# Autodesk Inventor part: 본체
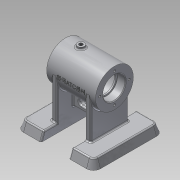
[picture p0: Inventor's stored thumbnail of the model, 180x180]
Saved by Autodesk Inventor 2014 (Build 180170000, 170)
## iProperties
Created: 2016-07
Part Number: 본체
Material: 알루미늄 6061
Document SubType Name: Modeling
Designer: net
Density: 2.71 g/cm^3
Appearance: 알루미늄 - 평지
Mass: 505.561 g
Surface Area: 530.336 cm^2
Volume: 186.554 cm^3
Author: net
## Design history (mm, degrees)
sketch "스케치1"
  geometry: C1 r 27 at (0, 0); 1 further point
  constraints: 1 centre point, 1 coincident
  dimensions: "d0" = 54 diameter of C1
extrude "돌출1" new body sketch "스케치1" stored distance "d1" = 70; taper "d2" = 0 deg
sketch "스케치2"
  geometry: C1 r 22 at (0, 0); 1 further point
  constraints: 1 centre point, 1 coincident
  dimensions: "d3" = 44 diameter of C1
extrude "돌출2" cut sketch "스케치2" stored distance "d4" = 42; taper "d5" = 0 deg
sketch "스케치3"
  geometry: C1 r 27 at (0, 0) reference; C2 r 14 at (0, 0)
  constraints: 1 centre point, 1 coincident
  dimensions: "d6" = 28 diameter of C2
extrude "돌출3" cut sketch "스케치3" stored distance "d7" = 42; taper "d8" = 0 deg
sketch "스케치4"
  geometry: C1 r 14 at (0, 0) reference; C2 r 27 at (0, 0) reference; C3 r 16 at (0, 0)
  constraints: 1 centre point, 1 coincident
  dimensions: "d9" = 32 diameter of C3
extrude "돌출4" cut sketch "스케치4" distance "d10" = 12; taper "d11" = 0 deg
sketch "스케치5"
  geometry: C1 r 14 at (0, 0) reference; C2 r 27 at (0, 0) reference; C3 r 16 at (0, 0)
  constraints: 1 centre point, 1 coincident
  dimensions: "d12" = 32 diameter of C3
extrude "돌출5" cut sketch "스케치5" distance "d13" = 12; taper "d14" = 0 deg
node "작업 평면1"
sketch "스케치6"
  geometry: L1 (-35, 27)-(-35, -27) reference; L2 (35, -27)-(35, 27) reference; L3 (-35, 0)-(35, 0); C1 r 5 at (-13, 0); 1 further point
  constraints: 2 end point, 2 midpoint, 1 centre point, 1 point on line
  dimensions: "d16" = 10 diameter of C1; "d17" = 22 distance of L3.start C1.centre
extrude "돌출6" join sketch "스케치6" stored distance "d18" = 12; taper "d19" = 0 deg
node "작업 평면3"
  node "작업 평면2"
sketch "스케치7"
  geometry: C1 r 6 at (0, 0); 1 further point
  constraints: 1 centre point, 1 coincident
  dimensions: "d22" = 12 diameter of C1
extrude "돌출7" join sketch "스케치7" stored distance "d23" = 10; taper "d24" = 0 deg
node "작업 평면4"
sketch "스케치9"
  geometry: L1 (-55, 50)-(-20, 50); L2 (-20, -50)-(-55, -50); L3 (-55, -50)-(-55, 50); L4 (0, 29.989)-(0, -29.989); L5 (55, 50)-(20, 50); L6 (55, -50)-(55, 50); L7 (20, -50)-(55, -50); L8 (-20, 50)-(20, 50); L9 (-20, -50)-(20, -50); C1 r 3 at (-42.5, 37.5); C2 r 3 at (-42.5, -37.5); C3 r 3 at (42.5, 37.5); C4 r 3 at (42.5, -37.5); 3 further points
  constraints: 18 end point, 6 symmetric about line, 4 centre point, 3 parallel, 2 midpoint, 1 coincident, 1 collinear, 1 horizontal, 1 horizontal alignment, 2 other
  dimensions: "d26" = 55 distance between parallel lines of L4 L3; "d27" = 100 distance of L2.end L1.start; "d28" = 35 distance of L1.start L1.end; "d29" = 6 diameter of C1; "d30" = 6 diameter of C2; "d31" = 12.5 distance from line of L2 C2.centre; "d32" = 12.5 distance from line of L3 C2.centre; "d33" = 12.5 distance from line of L1 C1.centre; "d34" = 12.5 distance from line of L3 C1.centre
extrude "돌출9" join sketch "스케치9" distance "d37" = 12; taper "d38" = -20 deg
sketch "스케치12"
  geometry: L1 (-23, 16)-(-35, 16) reference; L2 (-35, 16)-(-35, 27) reference; L3 (-35, 27)-(8, 27) reference; L4 (8, 27)-(8, 30) reference; L5 (8, 30)-(18, 30) reference; L6 (18, 30)-(18, 27) reference; L7 (18, 27)-(35, 27) reference; L8 (35, 27)-(35, 16) reference; L9 (35, 16)-(23, 16) reference; L10 (23, 16)-(23, 14) reference; L11 (23, 14)-(21, 14) reference; L12 (21, 14)-(21, 22) reference; L13 (21, 22)-(-21, 22) reference; L14 (-21, 22)-(-21, 14) reference; L15 (-21, 14)-(-23, 14) reference; L16 (-23, 14)-(-23, 16) reference; L17 (-35, -16)-(-23, -16) reference; L18 (-23, -16)-(-23, -14) reference; L19 (-23, -14)-(-21, -14) reference; L20 (-21, -14)-(-21, -22) reference; L21 (-21, -22)-(21, -22) reference; L22 (21, -22)-(21, -14) reference; L23 (21, -14)-(23, -14) reference; L24 (23, -14)-(23, -16) reference; L25 (23, -16)-(35, -16) reference; L26 (35, -16)-(35, -27) reference; L27 (35, -27)-(-35, -27) reference; L28 (-35, -27)-(-35, -16) reference; L29 (50.632, -58)-(55, -70) reference; L30 (55, -70)-(-55, -70) reference; L31 (-55, -70)-(-50.632, -58) reference; L32 (-50.632, -58)-(50.632, -58) reference; L33 (0, -70)-(0, 22); L34 (-20, -70)-(20, -70); L35 (20, -70)-(20, -58); L36 (20, -58)-(-20, -58); L37 (-20, -58)-(-20, -70); 1 further point
  constraints: 10 end point, 2 midpoint, 2 parallel, 2 point on line, 1 horizontal, 1 perpendicular
  dimensions: "d39" = 40 distance between parallel lines of L35 L37; "d40" = 20 distance between parallel lines of L33 L37
extrude "돌출10" cut sketch "스케치12" stored distance "d41" = 12; taper "d42" = 0 deg
sketch "스케치13"
  geometry: L1 (20, 50)-(20, -50) reference; L2 (-20, -50)-(-20, 50) reference; L3 (-20, 50)-(-55, 50) reference; L4 (-55, 50)-(-55, -50) reference; L5 (-55, -50)-(-20, -50) reference; L6 (-20, 50)-(20, 50); L7 (0, 50)-(0, -50); L8 (-20, 27)-(-28, 27); L9 (-28, 27)-(-28, -27); L10 (-28, -27)-(-20, -27); L11 (-20, -27)-(-20, 27); L12 (28, -27)-(20, -27); L13 (20, -27)-(20, 27); L14 (20, 27)-(28, 27); L15 (28, 27)-(28, -27); C1 r 3 at (-42.5, -37.5) reference; C2 r 3 at (-42.5, 37.5) reference; 1 further point
  constraints: 20 end point, 4 symmetric about line, 3 perpendicular, 2 parallel, 1 horizontal, 1 midpoint, 1 point on line
  dimensions: "d43" = 54 distance of L10.end L8.start; "d44" = 27 distance from line of point (0, 0) L8 (= 0.5 x d43); "d45" = 8 distance of L8.start L8.end
extrude "돌출11" join sketch "스케치13" stored distance "d46" = 12; taper "d47" = 0 deg
sketch "스케치14"
  geometry: L1 (23, -16)-(35, -16) reference; L2 (35, -16)-(35, -27) reference; L3 (35, -27)-(28, -27) reference; L4 (28, -27)-(28, -58) reference; L5 (28, -58)-(50.632, -58) reference; L6 (50.632, -58)-(55, -70) reference; L7 (55, -70)-(20, -70) reference; L8 (20, -70)-(20, -27) reference; L9 (20, -27)-(-20, -27) reference; L10 (-20, -27)-(-20, -70) reference; L11 (-20, -70)-(-55, -70) reference; L12 (-55, -70)-(-50.632, -58) reference; L13 (-50.632, -58)-(-28, -58) reference; L14 (-28, -58)-(-28, -27) reference; L15 (-28, -27)-(-35, -27) reference; L16 (-35, -27)-(-35, -16) reference; L17 (-35, -16)-(-23, -16) reference; L18 (-23, -16)-(-23, -14) reference; L19 (-23, -14)-(-21, -14) reference; L20 (-21, -14)-(-21, -22) reference; L21 (-21, -22)-(21, -22) reference; L22 (21, -22)-(21, -14) reference; L23 (21, -14)-(23, -14) reference; L24 (23, -14)-(23, -16) reference; L25 (35, 16)-(23, 16) reference; L26 (23, 16)-(23, 14) reference; L27 (23, 14)-(21, 14) reference; L28 (21, 14)-(21, 22) reference; L29 (21, 22)-(-21, 22) reference; L30 (-21, 22)-(-21, 14) reference; L31 (-21, 14)-(-23, 14) reference; L32 (-23, 14)-(-23, 16) reference; L33 (-23, 16)-(-35, 16) reference; L34 (-35, 16)-(-35, 27) reference; L35 (-35, 27)-(8, 27) reference; L36 (8, 27)-(8, 30) reference; L37 (8, 30)-(18, 30) reference; L38 (18, 30)-(18, 27) reference; L39 (18, 27)-(35, 27) reference; L40 (35, 27)-(35, 16) reference; L41 (-20, -48)-(20, -48); 1 further point
  constraints: 2 end point, 2 point on line, 1 perpendicular
  dimensions: "d48" = 21 distance between parallel lines of L15 L41
feature "리브1" sketch "스케치14" dims "d49" = 1, "d50" = 8, "d51" = 0, "d52" = 0, "d53" = 1, "d54" = 1
sketch "스케치15"
  geometry: L1 (10, 53.404)-(55, 53.404) reference; L2 (55, 53.404)-(55, 42.194) reference; L3 (55, 42.194)-(43, 42.194) reference; L4 (43, 42.194)-(43, 40.118) reference; L5 (43, 40.118)-(41, 40.118) reference; L6 (41, 40.118)-(41, 48.335) reference; L7 (41, 48.335)-(-1, 48.335) reference; L8 (-1, 48.335)-(-1, 40.118) reference; L9 (-1, 40.118)-(-3, 40.118) reference; L10 (-3, 40.118)-(-3, 42.194) reference; L11 (-3, 42.194)-(-15, 42.194) reference; L12 (-15, 42.194)-(-15, 53.404) reference; L13 (-15, 53.404)-(4, 53.404) reference; L14 (4, 53.404)-(4, 56.702) reference; L15 (4, 56.702)-(10, 56.702) reference; L16 (10, 56.702)-(10, 53.404) reference; L17 (0, -43.298)-(-35, -43.298) reference; L18 (-35, -43.298)-(-30.632, -31.298) reference; L19 (-30.632, -31.298)-(-8, -31.298) reference; L20 (-8, -31.298)-(-8, 0) reference; L21 (-8, 0)-(-15, 0) reference; L22 (-15, 0)-(-15, 11.21) reference; L23 (-15, 11.21)-(-3, 11.21) reference; L24 (-3, 11.21)-(-3, 13.286) reference; L25 (-3, 13.286)-(-1, 13.286) reference; L26 (-1, 13.286)-(-1, 5.069) reference; L27 (-1, 5.069)-(41, 5.069) reference; L28 (41, 5.069)-(41, 13.286) reference; L29 (41, 13.286)-(43, 13.286) reference; L30 (43, 13.286)-(43, 11.21) reference; L31 (43, 11.21)-(55, 11.21) reference; L32 (55, 11.21)-(55, 0) reference; L33 (55, 0)-(48, 0) reference; L34 (48, 0)-(48, -31.298) reference; L35 (48, -31.298)-(70.632, -31.298) reference; L36 (70.632, -31.298)-(75, -43.298) reference; L37 (75, -43.298)-(40, -43.298) reference; L38 (40, -43.298)-(40, -21.298) reference; L39 (40, -21.298)-(0, -21.298) reference; L40 (0, 0)-(0, -21.298) reference; L41 (40, 0)-(0, 0) reference; L42 (40, -21.298)-(40, 0) reference; L43 (0, -21.298)-(0, -43.298) reference; L44 (8.5, -11.298)-(31.5, -11.298); L45 (20, -21.298)-(20, 48.335); L46 (12, -7.798)-(28, -7.798); L47 (12, -14.798)-(28, -14.798); A1 r 3.5 centre (12, -11.298) between (12, -7.798) and (12, -14.798); A2 r 3.5 centre (28, -11.298) between (28, -14.798) and (28, -7.798); 2 further points
  constraints: 8 end point, 6 point on circle, 4 tangent, 3 midpoint, 3 point on line, 2 centre point, 1 equal radius, 1 perpendicular
  dimensions: "d55" = 32 distance between parallel lines of L37 L44; "d56" = 23 distance of L44.start L44.end; "d57" = 7 diameter of A1; "d58" = 11.5 distance of point (20, -11.298) L44.start (derived)
extrude "돌출12" cut sketch "스케치15" stored distance "d59" = 0; taper "d60" = 0 deg
node "작업 평면5"
sketch "스케치16"
  geometry: L1 (-35, 27)-(-35, -27) reference; L2 (35, -27)-(35, 27) reference; L3 (-35, 27)-(35, 27) reference; L4 (-35, -27)-(35, -27) reference; L5 (0, 27)-(0, -27); L6 (-35, 0)-(35, 0); L7 (-20.065, 7.274)-(20.065, 7.274); L8 (20.065, 7.274)-(20.065, -7.274); L9 (20.065, -7.274)-(-20.065, -7.274); L10 (-20.065, -7.274)-(-20.065, 7.274); L11 (-20.065, 0)-(20.065, 0); L12 (0, 7.274)-(0, -7.274); 1 further point
  constraints: 8 end point, 8 midpoint, 2 collinear, 2 other
  dimensions: "d62" = 35 distance between parallel lines of L1 L5 (derived); "d63" = 27 distance between parallel lines of L3 L6 (derived)
feature "엠보싱1" sketch "스케치16" dims "d9" = 32, "d64" = 0.5, "d65" = 0
sketch "스케치19"
  geometry: L1 (20, 50)-(20, -50) reference; L2 (20, 50)-(55, 50); L3 (55, 50)-(55, -50); L4 (55, -50)-(20, -50); L5 (20, -27)-(28, -27) reference; L6 (28, -27)-(28, 27) reference; L7 (28, 27)-(20, 27) reference; L8 (20, -27)-(28, -27); L9 (28, 27)-(28, -27); L10 (28, 27)-(20, 27); L11 (20, -50)-(20, -27); L12 (20, 27)-(20, 50); L13 (-55, -50)-(-20, -50) reference; L14 (0, 0)-(0, -58.48); L15 (-55, 50)-(-55, -50); L16 (-55, -50)-(-20, -50); L17 (-28, -27)-(-28, 27); L18 (-28, 27)-(-28, -27); L19 (-20, -27)-(-28, -27); L20 (-20, -27)-(-28, -27); L21 (-20, -50)-(-20, -27); L22 (-28, 27)-(-20, 27); L23 (-20, 27)-(-20, 50); L24 (-20, 50)-(-55, 50); L25 (-28, 27)-(-20, 27); C1 r 3 at (42.5, 37.5) reference; C2 r 3 at (42.5, -37.5) reference; 3 further points
  constraints: 40 end point, 8 symmetric about line, 3 parallel, 3 perpendicular, 2 collinear, 1 horizontal
extrude "돌출15" cut sketch "스케치19" distance "d71" = 12; taper "d72" = 0 deg
sketch "스케치20"
  geometry: L1 (-28, -27)-(-20, -27) reference; L2 (-20, -27)-(-20, 27) reference; L3 (-20, 27)-(-28, 27) reference; L4 (-28, 27)-(-28, -27) reference; L5 (-20, 50)-(-45, 50); L6 (-55, 40)-(-55, -40); L7 (-45, -50)-(-20, -50); L8 (-20, -50)-(-20, 50); L9 (0, 0)-(0, -50); L10 (20, 50)-(45, 50); L11 (55, 40)-(55, -40); L12 (45, -50)-(20, -50); L13 (20, -50)-(20, 50); A1 r 10 centre (-45, 40) between (-45, 50) and (-55, 40); A2 r 10 centre (-45, -40) between (-55, -40) and (-45, -50); A3 r 10 centre (45, 40) between (55, 40) and (45, 50); A4 r 10 centre (45, -40) between (45, -50) and (55, -40); 4 further points
  constraints: 18 end point, 10 symmetric about line, 8 point on circle, 8 point on line, 4 centre point, 4 tangent, 3 parallel, 1 collinear, 1 equal radius, 1 horizontal, 1 perpendicular, 2 other
  dimensions: "d73" = 100 distance of point (-55, 50) point (-55, -50); "d74" = 35 distance of L5.start point (-55, 50); "d75" = 50 distance from line of L9.start L5 (= 0.5 x d73); "d76" = 10 radius of A1
node "작업 평면6"
sketch "스케치22" dims "d81" = 42
  geometry: L1 (0, 0)-(21, 0); C1 r 27 at (0, 0) reference
  constraints: 2 end point, 1 coincident, 1 horizontal, 1 horizontal alignment, 2 other
sketch "스케치23" dims "d82" = 42
  geometry: L1 (-21, 0)-(0, 0); C1 r 16 at (0, 0) reference
  constraints: 2 end point, 1 coincident, 1 horizontal, 1 horizontal alignment, 2 other
hole "구멍1" sketch "스케치23" at (-21, 0) diameter "d83" = 3.242; stored, may be unused: countersink angle "d87" = 90 deg, drill point angle "d89" = 118 deg; dims "d84" = 8, "d85" = 4, "d86" = 2, "d88" = 10
hole "구멍2" sketch "스케치22" diameter "d90" = 3.242; stored, may be unused: countersink angle "d94" = 90 deg, drill point angle "d96" = 118 deg; dims "d91" = 8, "d92" = 4, "d93" = 2, "d95" = 10
sketch "스케치24"
  geometry: C1 r 5 at (0, 0) reference; 1 further point
sketch "스케치25"
  geometry: C1 r 6 at (0, 0) reference
hole "구멍3" sketch "스케치24" diameter "d100" = 5.188; stored, may be unused: countersink angle "d104" = 90 deg, drill point angle "d106" = 118 deg; dims "d101" = 48, "d102" = 4, "d103" = 2, "d105" = 10
hole "구멍4" sketch "스케치25" diameter "d107" = 5.188; stored, may be unused: countersink angle "d111" = 90 deg, drill point angle "d113" = 118 deg; dims "d108" = 35, "d109" = 4, "d110" = 2, "d112" = 10
fillet "모깎기1" dims "d114" = 3, "d115" = 0.3
chamfer "모따기1" distance "d116" = 1; stored, may be unused: second distance "d117" = 2, angle "d118" = 45 deg
fillet "모깎기2" dims "d119" = 2
extrude "돌출17" join sketch "스케치20" distance "d120" = 12; taper "d121" = 0 deg
feature "면 기울기2" dims angle "d122" = 20 deg
feature "면 기울기3" dims angle "d123" = -20 deg
fillet "모깎기3" dims "d124" = 2
fillet "모깎기4" dims "d125" = 2
fillet "모깎기5" dims "d126" = 2
fillet "모깎기6" dims "d127" = 2
fillet "모깎기7" dims "d128" = 2
node "솔리드1"
pattern_circular "원형 패턴1" dims angle "d98" = 360 deg
node "투영된 루프1"
node "절단 모서리 투영3"
node "절단 모서리 투영4"
node "절단 모서리 투영5"
other parameters: "d20" = 32 deg, "d61" = -55, "d80" = -12
